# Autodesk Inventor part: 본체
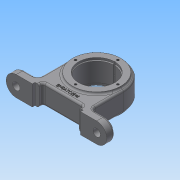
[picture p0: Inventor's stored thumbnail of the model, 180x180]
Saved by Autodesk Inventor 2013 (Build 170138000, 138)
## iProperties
Created: 2019-05
Part Number: 본체
Material: 일반
Document SubType Name: Modeling
Designer: Administrator
Density: 1 g/cm^3
Author: Administrator
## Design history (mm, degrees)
sketch "스케치3"
  geometry: L1 (40, 4.967)-(40, -37.033); L2 (-40, -37.033)-(-40, 4.967); L3 (75, -43.033)-(75, -55.033); L4 (-75, -55.033)-(-75, -43.033); L5 (-75, -43.033)-(-46, -43.033); L6 (46, -43.033)-(75, -43.033); L7 (36, -51.033)-(36, -55.033); L8 (-36, -55.033)-(-36, -51.033); L9 (75, -55.033)-(36, -55.033); L10 (-36, -55.033)-(-75, -55.033); L11 (-30, -45.033)-(30, -45.033); L12 (30, -45.033)-(30, -51.033); L13 (-30, -51.033)-(-30, -45.033); L14 (-36, -51.033)-(-30, -51.033); L15 (30, -51.033)-(36, -51.033); C1 r 26 at (0, 4.967); A1 r 40 centre (0, 4.967) between (40, 4.967) and (-40, 4.967); A2 r 6 centre (-46, -37.033) between (-46, -43.033) and (-40, -37.033); A3 r 6 centre (46, -37.033) between (40, -37.033) and (46, -43.033); 3 further points
  constraints: 30 end point, 8 parallel, 6 point on circle, 5 horizontal, 5 perpendicular, 4 centre point, 4 tangent, 2 vertical alignment, 1 coincident, 1 equal radius, 1 horizontal alignment
  dimensions: "d12" = 80 diameter of A1; "d16" = 150 distance of L3.end L4.start; "d17" = 12 distance of L3.start L3.end; "d22" = 10 distance between parallel lines of L11 L10; "d23" = 4 distance between parallel lines of L10 L14; "d24" = 60 distance between parallel lines of L13 L12; "d25" = 72 distance between parallel lines of L7 L8; "d26" = 6 radius of A2; "d27" = 52 diameter of C1
extrude "돌출1" new body sketch "스케치3" distance "d28" = 15; taper "d30" = 0 deg; dims "d29" = 15, "d31" = 0
fillet "모깎기1" dims "d32" = 15
sketch "스케치4"
  geometry: C1 r 9 at (-14, 15); A1 r 15 centre (-14, 15) between (-14, 30) and (-14, 0) reference; 1 further point
  constraints: 1 centre point, 1 coincident
  dimensions: "d33" = 18 diameter of C1
extrude "돌출2" join sketch "스케치4" distance "d34" = 3; taper "d35" = 0 deg
hole "구멍1" diameter "d38" = 11; stored, may be unused: countersink angle "d42" = 90 deg, drill point angle "d44" = 118 deg; dims "d36" = 10, "d37" = 10, "d39" = 6, "d40" = 4, "d41" = 2, "d43" = 8
fillet "모깎기2" dims "d45" = 3
fillet "모깎기3" dims "d46" = 3
chamfer "모따기1" distance "d47" = 1; stored, may be unused: second distance "d48" = 2, angle "d49" = 45 deg
chamfer "모따기2" distance "d50" = 1; stored, may be unused: second distance "d51" = 2, angle "d52" = 45 deg
sketch "스케치5"
  geometry: C1 r 27 at (0, 4.967) reference; C2 r 36 at (0, 4.967); 1 further point
  constraints: 1 centre point, 1 coincident
  dimensions: "d53" = 72 diameter of C2
extrude "돌출3" join sketch "스케치5" distance "d54" = 3; taper "d55" = 0 deg
fillet "모깎기4" dims "d56" = 3
fillet "모깎기5" dims "d57" = 3
sketch "스케치6"
  geometry: L1 (0, 5.503)-(0, 36.503); L2 (0, 5.503)-(31, 5.503); 1 further point
  constraints: 4 end point, 1 horizontal, 1 perpendicular, 1 vertical
  dimensions: "d58" = 31 distance of L1.start L1.end; "d59" = 90 deg angle of L2 L1 (derived)
hole "구멍2" sketch "스케치6" at (0, 36.503) diameter "d60" = 3.459; stored, may be unused: countersink angle "d64" = 90 deg, drill point angle "d66" = 118 deg; dims "d61" = 6, "d62" = 4, "d63" = 2, "d65" = 8
fillet "모깎기6" dims "d70" = 3
sketch "스케치7"
  geometry: C1 r 1.5 at (0, 26); 2 further points
  constraints: 1 centre point, 1 vertical alignment, 1 other
  dimensions: "d71" = 3 diameter of C1
extrude "돌출4" cut sketch "스케치7" stored distance "d72" = 3; taper "d73" = 0 deg
node "작업 평면2"
sketch "스케치8"
  geometry: 1 further point
hole "구멍3" sketch "스케치8" at (0, 0) diameter "d74" = 4.917; stored, may be unused: countersink angle "d78" = 90 deg, drill point angle "d80" = 118 deg; dims "d75" = 8, "d76" = 7, "d77" = 1, "d79" = 10
sketch "스케치9"
  geometry: C1 r 1 at (0, 0); 1 further point
  constraints: 1 centre point, 1 coincident
  dimensions: "d81" = 2 diameter of C1
extrude "돌출5" cut sketch "스케치9" stored distance "d82" = 3; taper "d83" = 0 deg
sketch "스케치10"
  geometry: L1 (-27, -45.033)-(27, -45.033) reference; 4 further points
  constraints: 1 midpoint, 1 vertical alignment, 1 other
  dimensions: "d84" = 7 distance from line of L1 point (-16.708, -38.033)
feature "엠보싱1" sketch "스케치10" dims "d85" = 0.5, "d86" = 0
node "솔리드1"
mirror "대칭1"
mirror "대칭2"
pattern_circular "원형 패턴1" dims angle "d68" = 360 deg
mirror "대칭3"
